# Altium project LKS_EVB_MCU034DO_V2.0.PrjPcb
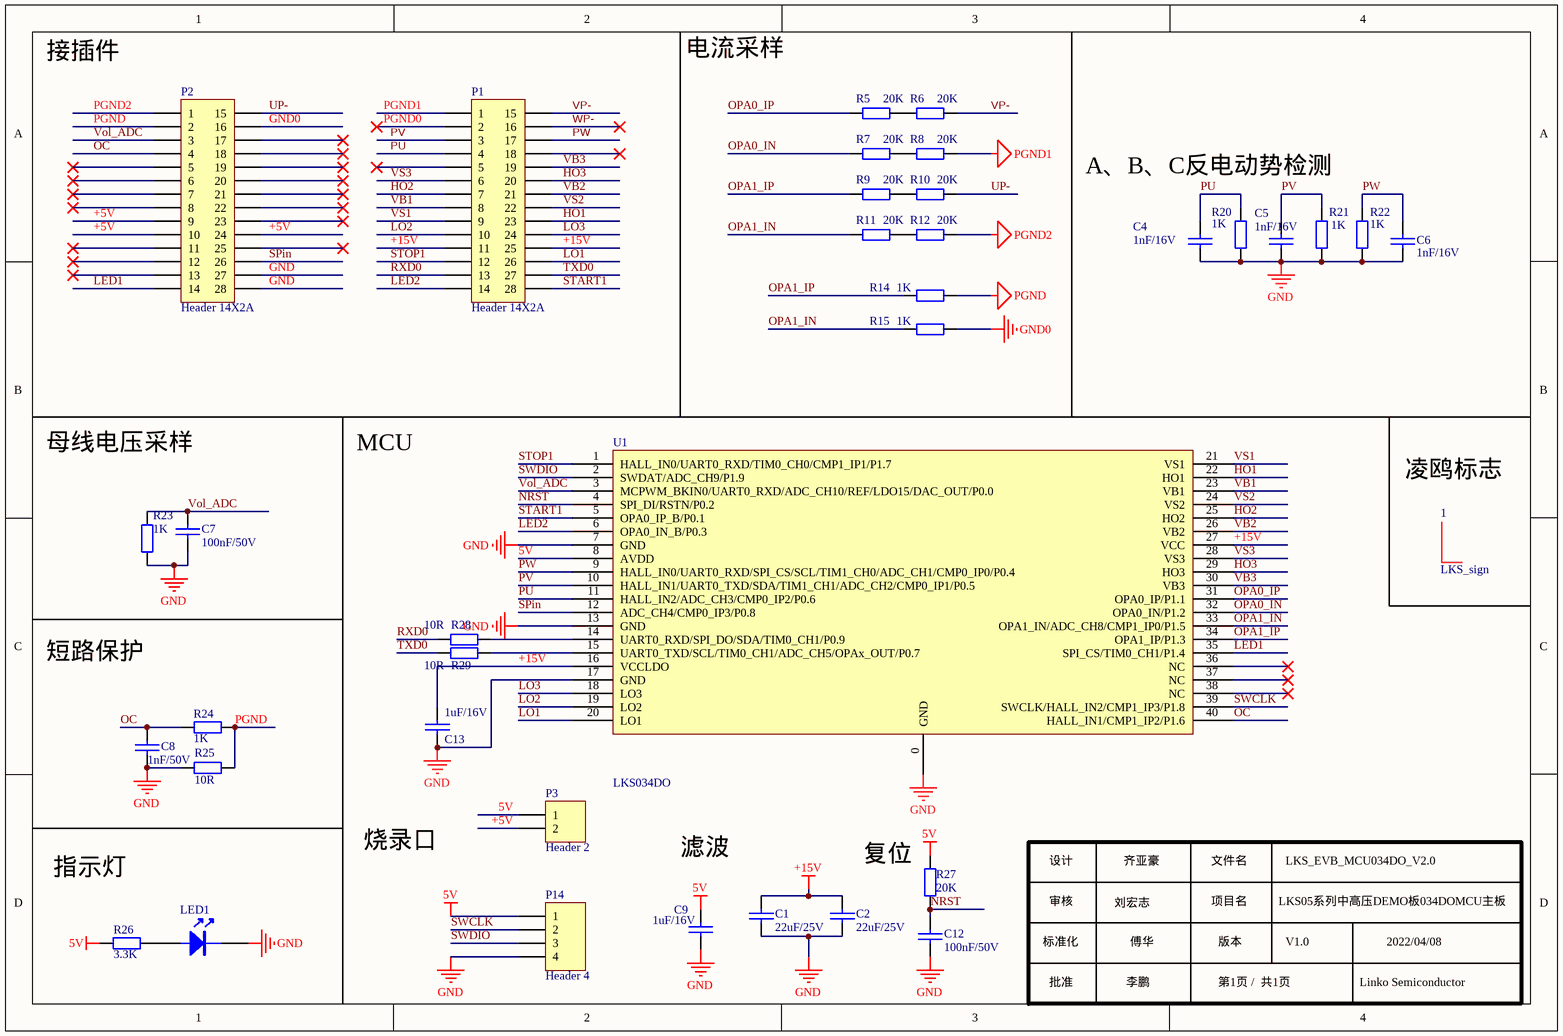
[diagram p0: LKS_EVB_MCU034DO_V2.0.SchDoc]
1 sheet, 37 parts. Net scope: global (net labels, ports and power ports of the same name join across sheets).
Board file: LKS_EVB_MCU034DO_V2.0.PcbDoc

## Sheet LKS_EVB_MCU034DO_V2.0.SchDoc
size A4; SheetNumber: 1; SheetTotal: 1

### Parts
1  LKS_sign  [LKS_LOGO2]
C1  22uF/25V  [1206C]
C2  22uF/25V  [1206C]
C4  1nF/16V  [0603C]
C5  1nF/16V  [0603C]
C6  1nF/16V  [0603C]
C7  100nF/50V  [0603C]
C8  1nF/50V  [0603C]
C9  1uF/16V  [0603C]
C12  100nF/50V  [0603C]
C13  1uF/16V  [0603C]
LED1  LED  [0603D]  (value not drawn)
P1  Header 14X2A  [HDR2 2X14 底层]
P2  Header 14X2A  [HDR2 2X14 底层]
P3  Header 2  [HDR1X2]
P14  Header 4  [HDR 1X4]
R5  20K  [0603R]
R6  20K  [0603R]
R7  20K  [0603R]
R8  20K  [0603R]
R9  20K  [0603R]
R10  20K  [0603R]
R11  20K  [0603R]
R12  20K  [0603R]
R14  1K  [0603R]
R15  1K  [0603R]
R20  1K  [0603R]
R21  1K  [0603R]
R22  1K  [0603R]
R23  1K  [0603R]
R24  1K  [0603R]
R25  10R  [0603R]
R26  3.3K  [0603R]
R27  20K  [0603R]
R28  10R  [0603R]
R29  10R  [0603R]
U1  LKS034DO  [QFN40]

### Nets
5V: C9.2 P3.1 P14.1 R26.2 R27.1 U1.8(AVDD)
+15V: C1.1 C2.1 C13.1 P1.11 P1.25 U1.16(VCCLDO) U1.27(VCC)
GND: C1.2 C2.2 C4.2 C5.2 C6.2 C7.1 C8.1 C9.1 C12.2 C13.2 LED1.2(K) P2.27 P2.28 P14.4 R20.2 R21.2 R22.2 R23.1 R25.2 U1.0(GND) U1.7(GND) U1.13(GND) U1.17(GND)
GND0: P2.16 R15.1
PGND: P2.2 R14.1 R24.2 R25.1
PGND1: P1.1 R8.1
PGND2: P2.1 R12.1
+5V: P2.9 P2.10 P2.24 P3.2
HO1: P1.23 U1.22(HO1)
HO2: P1.7 U1.25(HO2)
HO3: P1.20 U1.29(HO3)
LED1: P2.14 U1.35(SPI_CS/TIM0_CH1/P1.4)
LED2: P1.14 U1.6(OPA0_IN_B/P0.3)
LO1: P1.26 U1.20(LO1)
LO2: P1.10 U1.19(LO2)
LO3: P1.24 U1.18(LO3)
NRST: C12.1 R27.2 U1.4(SPI_DI/RSTN/P0.2)
OC: C8.2 P2.4 R24.1 U1.40(HALL_IN1/CMP1_IP2/P1.6)
OPA0_IN: R7.2 U1.32(OPA0_IN/P1.2)
OPA0_IP: R5.2 U1.31(OPA0_IP/P1.1)
OPA1_IN: R11.2 R15.2 U1.33(OPA1_IN/ADC_CH8/CMP1_IP0/P1.5)
OPA1_IP: R9.2 R14.2 U1.34(OPA1_IP/P1.3)
PGND0: P1.2
PU: C4.1 P1.4 R20.1 U1.11(HALL_IN2/ADC_CH3/CMP0_IP2/P0.6)
PV: C5.1 P1.3 R21.1 U1.10(HALL_IN1/UART0_TXD/SDA/TIM1_CH1/ADC_CH2/CMP0_IP1/P0.5)
PW: C6.1 P1.17 R22.1 U1.9(HALL_IN0/UART0_RXD/SPI_CS/SCL/TIM1_CH0/ADC_CH1/CMP0_IP0/P0.4)
RXD0: P1.13 R28.1
SPin: P2.26 U1.12(ADC_CH4/CMP0_IP3/P0.8)
START1: P1.28 U1.5(OPA0_IP_B/P0.1)
STOP1: P1.12 U1.1(HALL_IN0/UART0_RXD/TIM0_CH0/CMP1_IP1/P1.7)
SWCLK: P14.2 U1.39(SWCLK/HALL_IN2/CMP1_IP3/P1.8)
SWDIO: P14.3 U1.2(SWDAT/ADC_CH9/P1.9)
TXD0: P1.27 R29.1
UP-: P2.15 R10.1
VB1: P1.8 U1.23(VB1)
VB2: P1.21 U1.26(VB2)
VB3: P1.19 U1.30(VB3)
Vol_ADC: C7.2 P2.3 R23.2 U1.3(MCPWM_BKIN0/UART0_RXD/ADC_CH10/REF/LDO15/DAC_OUT/P0.0)
VP-: P1.15 R6.1
VS1: P1.9 U1.21(VS1)
VS2: P1.22 U1.24(VS2)
VS3: P1.6 U1.28(VS3)
WP-: P1.16
NetLED1_1: LED1.1(A) R26.1
NetR5_1: R5.1 R6.2
NetR7_1: R7.1 R8.2
NetR9_1: R9.1 R10.2
NetR11_1: R11.1 R12.2
NetR28_2: R28.2 U1.14(UART0_RXD/SPI_DO/SDA/TIM0_CH1/P0.9)
NetR29_2: R29.2 U1.15(UART0_TXD/SCL/TIM0_CH1/ADC_CH5/OPAx_OUT/P0.7)

Not connected (* = marked no-connect by the designer): P1 5* 18*; P2 5* 6* 7* 8* 11* 12* 13* 17* 18* 19* 20* 21* 22* 23* 25*; U1 36(NC)* 37(NC)* 38(NC)*

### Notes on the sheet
- 接插件
- 母线电压采样
- (near 1) 凌鸥标志
- 短路保护
- 烧录口
- 指示灯
- 滤波
- 复位
- 设计
- 审核
- 刘宏志
- 齐亚豪
- 文件名
- 项目名
- LKS05系列中高压DEMO板034DOMCU主板
- LKS_EVB_MCU034DO_V2.0
- 标准化
- 批准
- 李鹏
- 傅华
- 版本
- 第1页 /  共1页
- V1.0
- Linko Semiconductor
- 2022/04/08
- Labels drawn without touching a wire or pin: A、B、C反电动势检测, MCU, 电流采样

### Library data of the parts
C1 C2 = Capacitor: Capacitor --贴片电容
C4-C6 C13 = CAP: Capacitor
C7-C9 C12 = C: Capacitor
LED1 = LED: LED_Light
P1 P2 = Header 14X2A: Header, 14-Pin, Dual row
P3 = Header 2: Header, 2-Pin
P14 = Header 4: Header, 4-Pin
R5-R12 R14 R15 R20-R25 R27-R29 = Res: Resistor; Value: K
R26 = Res: Resistor; Value: 330
U1 = LKS32MC034DOF6Q8: CHIP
